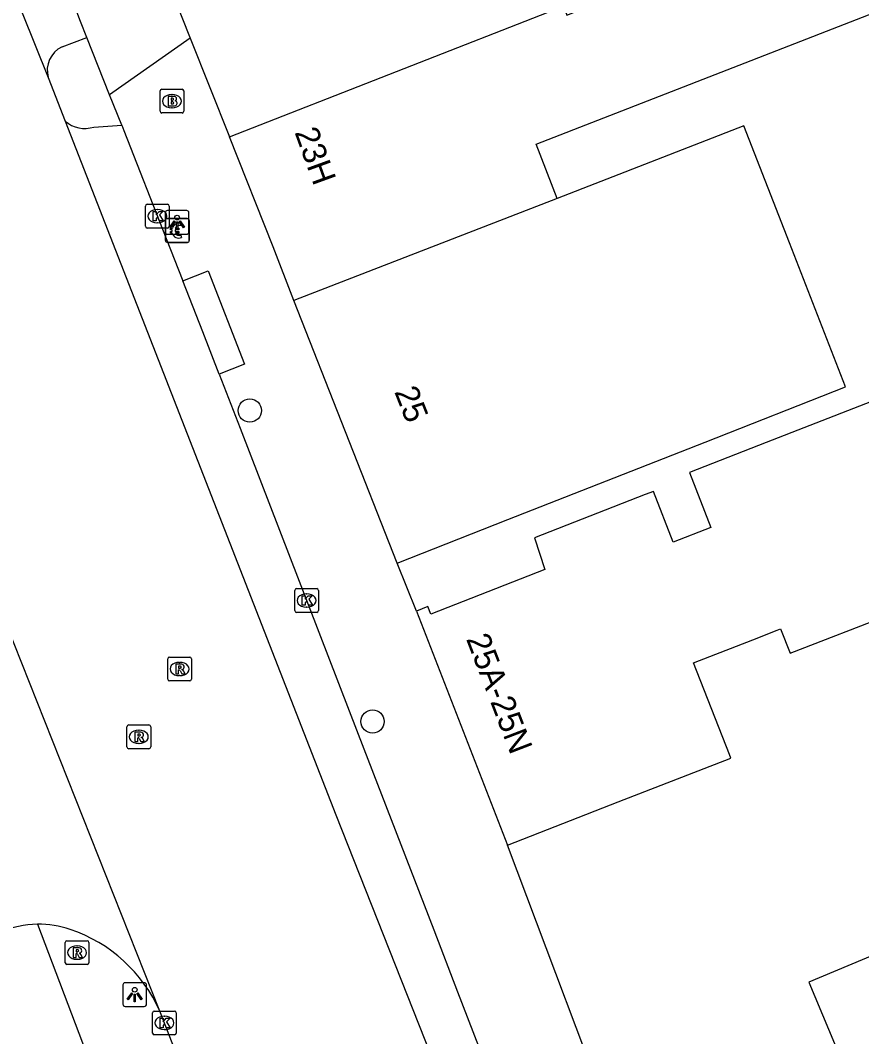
# Model space of a CAD drawing. Extents: x 161087 to 161922, y 382574 to 383873.
# Drawn here: x 161740.93 to 161776.33, y 382704.24 to 382747.01 of the extents above; entities that cross this region are included whole.
import ezdxf

# ---------------------------------------------------------------- set-up
doc = ezdxf.new("R2010")
doc.units = 0
for name, color, linetype in [('IMGEO_Betaalautomaat', 7, 'Continuous'), ('IMGEO_Boom', 7, 'Continuous'), ('IMGEO_Brandkraan', 7, 'Continuous'), ('IMGEO_Kolk', 7, 'Continuous'), ('IMGEO_Lichtpunt', 7, 'Continuous'), ('IMGEO_Pand', 7, 'Continuous'), ('IMGEO_Pand_nummerreeks', 7, 'Continuous'), ('IMGEO_Rijbaan_lokaal_open', 7, 'Continuous'), ('IMGEO_Rioolput', 7, 'Continuous'), ('IMGEO_Voetpad_open', 7, 'Continuous')]:
    doc.layers.add(name, color=color, linetype=linetype)

msp = doc.modelspace()

# ---------------------------------------------------------------- linework, layer by layer
at = {"layer": 'IMGEO_Betaalautomaat'}
for p, q in [((161747.04, 382737.742), (161747.04, 382738.583)), ((161747.04, 382738.583), (161747.04, 382737.742)), ((161747.115, 382738.666), (161747.956, 382738.666)), ((161747.956, 382738.666), (161747.115, 382738.666)), ((161748.039, 382738.592), (161748.039, 382737.751)), ((161748.039, 382737.751), (161748.039, 382738.592)), ((161747.323, 382738.13), (161747.323, 382738.198)), ((161747.444, 382738.198), (161747.444, 382738.13)), ((161747.702, 382738.471), (161747.685, 382738.371)), ((161747.689, 382737.965), (161747.711, 382737.878)), ((161747.965, 382737.667), (161747.124, 382737.667)), ((161747.124, 382737.667), (161747.965, 382737.667))]:
    msp.add_line(p, q, dxfattribs=at)
for points in [[(161747.323, 382738.198), (161747.254, 382738.198), (161747.254, 382738.267), (161747.333, 382738.267)], [(161747.328, 382738.061), (161747.254, 382738.061), (161747.254, 382738.13), (161747.323, 382738.13)], [(161747.455, 382738.267), (161747.602, 382738.267), (161747.602, 382738.198), (161747.444, 382738.198)], [(161747.444, 382738.13), (161747.602, 382738.13), (161747.602, 382738.061), (161747.458, 382738.061)]]:
    msp.add_lwpolyline(points, dxfattribs=at)
for centre, radius, start, end in [((161747.118, 382738.589), 0.0779, 92.4484, 184.2845), ((161747.118, 382738.589), 0.0779, 92.4484, 184.2845), ((161747.962, 382738.589), 0.0779, 2.4484, 94.2845), ((161747.962, 382738.589), 0.0779, 2.4484, 94.2845), ((161747.616, 382738.191), 0.293, 73.014, 165.0139), ((161747.622, 382738.204), 0.179, 69.3236, 159.5683), ((161747.118, 382737.745), 0.0779, 182.4484, 274.2845), ((161747.118, 382737.745), 0.0779, 182.4484, 274.2845), ((161747.589, 382738.116), 0.267, 191.8096, 297.0389), ((161747.622, 382738.131), 0.179, 202.7625, 291.8693), ((161747.962, 382737.745), 0.0779, 272.4484, 4.2845), ((161747.962, 382737.745), 0.0779, 272.4484, 4.2845)]:
    msp.add_arc(centre, radius, start, end, dxfattribs=at)
at = {"layer": 'IMGEO_Boom'}
for centre in [(161750.589, 382730.591), (161755.753, 382717.503)]:
    msp.add_circle(centre, 0.489, dxfattribs=at)
at = {"layer": 'IMGEO_Brandkraan'}
for p, q in [((161746.886, 382744.113), (161747.738, 382744.113)), ((161746.811, 382743.187), (161746.811, 382744.039)), ((161747.299, 382743.893), (161747.324, 382743.893)), ((161747.812, 382744.039), (161747.812, 382743.187)), ((161747.322, 382743.333), (161747.297, 382743.333)), ((161747.738, 382743.113), (161746.886, 382743.113))]:
    msp.add_line(p, q, dxfattribs=at)
for points in [[(161746.886, 382744.113), (161747.738, 382744.113)], [(161746.811, 382743.187), (161746.811, 382744.039)], [(161747.159, 382743.813), (161747.159, 382743.413), (161747.372, 382743.413)], [(161747.39, 382743.813), (161747.159, 382743.813)], [(161747.338, 382743.732), (161747.284, 382743.732), (161747.284, 382743.656)], [(161747.812, 382744.039), (161747.812, 382743.187)], [(161747.284, 382743.656), (161747.337, 382743.656)], [(161747.346, 382743.58), (161747.284, 382743.58), (161747.284, 382743.499)], [(161747.284, 382743.499), (161747.346, 382743.499)], [(161747.738, 382743.113), (161746.886, 382743.113)]]:
    msp.add_lwpolyline(points, dxfattribs=at)
for centre, radius, start, end in [((161746.888, 382744.037), 0.0765, 91.552, 178.448), ((161746.888, 382744.037), 0.0765, 91.552, 178.448), ((161747.736, 382744.037), 0.0765, 1.552, 88.448), ((161747.736, 382744.037), 0.0765, 1.552, 88.448), ((161747.339, 382743.694), 0.0379, 267.8285, 90.9355), ((161747.394, 382743.668), 0.145, 59.4692, 91.5367), ((161747.419, 382743.715), 0.0922, 285.5137, 58.1501), ((161747.347, 382743.539), 0.0404, 269.8759, 90.5077), ((161747.378, 382743.664), 0.251, 268.6676, 293.5347), ((161747.424, 382743.523), 0.105, 301.3115, 78.989), ((161746.888, 382743.189), 0.0765, 181.552, 268.448), ((161746.888, 382743.189), 0.0765, 181.552, 268.448), ((161747.736, 382743.189), 0.0765, 271.552, 358.448), ((161747.736, 382743.189), 0.0765, 271.552, 358.448)]:
    msp.add_arc(centre, radius, start, end, dxfattribs=at)
for centre, major_axis, ratio, start_param, end_param in [((161747.298, 382743.613), (-0.387, 0.002), 0.722429, 4.712389, 7.853982), ((161747.323, 382743.613), (-0.39, 0.002), 0.717154, 1.570796, 4.712389)]:
    msp.add_ellipse(centre, major_axis=major_axis, ratio=ratio, start_param=start_param, end_param=end_param, dxfattribs=at)
at = {"layer": 'IMGEO_Kolk'}
for p, q in [((161746.198, 382738.345), (161746.198, 382739.197)), ((161746.273, 382739.271), (161747.125, 382739.271)), ((161746.686, 382739.051), (161746.711, 382739.051)), ((161747.199, 382739.197), (161747.199, 382738.345)), ((161747.125, 382738.271), (161746.273, 382738.271)), ((161746.709, 382738.491), (161746.684, 382738.491)), ((161752.476, 382722.17), (161752.476, 382723.022)), ((161752.551, 382723.096), (161753.403, 382723.096)), ((161752.964, 382722.876), (161752.989, 382722.876)), ((161753.477, 382723.022), (161753.477, 382722.17)), ((161752.987, 382722.316), (161752.962, 382722.316)), ((161753.403, 382722.096), (161752.551, 382722.096)), ((161746.494, 382704.391), (161746.494, 382705.243)), ((161746.569, 382705.317), (161747.421, 382705.317)), ((161747.495, 382705.243), (161747.495, 382704.391)), ((161746.982, 382705.097), (161747.007, 382705.097)), ((161747.005, 382704.537), (161746.98, 382704.537)), ((161747.421, 382704.317), (161746.569, 382704.317))]:
    msp.add_line(p, q, dxfattribs=at)
for points in [[(161746.198, 382738.345), (161746.198, 382739.197)], [(161746.273, 382739.271), (161747.125, 382739.271)], [(161747.199, 382739.197), (161747.199, 382738.345)], [(161746.519, 382738.971), (161746.642, 382738.971), (161746.642, 382738.82), (161746.772, 382738.971), (161746.936, 382738.971), (161746.79, 382738.82), (161746.943, 382738.571), (161746.791, 382738.571), (161746.706, 382738.735), (161746.642, 382738.668), (161746.642, 382738.571), (161746.519, 382738.571), (161746.519, 382738.971)], [(161747.125, 382738.271), (161746.273, 382738.271)], [(161752.476, 382722.17), (161752.476, 382723.022)], [(161752.551, 382723.096), (161753.403, 382723.096)], [(161752.797, 382722.796), (161752.92, 382722.796), (161752.92, 382722.645), (161753.05, 382722.796), (161753.214, 382722.796), (161753.068, 382722.645), (161753.221, 382722.396), (161753.069, 382722.396), (161752.984, 382722.56), (161752.92, 382722.493), (161752.92, 382722.396), (161752.797, 382722.396), (161752.797, 382722.796)], [(161753.477, 382723.022), (161753.477, 382722.17)], [(161753.403, 382722.096), (161752.551, 382722.096)], [(161746.494, 382704.391), (161746.494, 382705.243)], [(161746.569, 382705.317), (161747.421, 382705.317)], [(161747.495, 382705.243), (161747.495, 382704.391)], [(161746.815, 382705.017), (161746.938, 382705.017), (161746.938, 382704.866), (161747.068, 382705.017), (161747.232, 382705.017), (161747.086, 382704.866), (161747.239, 382704.617), (161747.087, 382704.617), (161747.002, 382704.781), (161746.938, 382704.714), (161746.938, 382704.617), (161746.815, 382704.617), (161746.815, 382705.017)], [(161747.421, 382704.317), (161746.569, 382704.317)]]:
    msp.add_lwpolyline(points, dxfattribs=at)
for centre, start, end in [((161746.275, 382739.195), 91.552, 178.448), ((161746.275, 382739.195), 91.552, 178.448), ((161747.123, 382739.195), 1.552, 88.448), ((161747.123, 382739.195), 1.552, 88.448), ((161746.275, 382738.347), 181.552, 268.448), ((161746.275, 382738.347), 181.552, 268.448), ((161747.123, 382738.347), 271.552, 358.448), ((161747.123, 382738.347), 271.552, 358.448), ((161752.553, 382723.02), 91.552, 178.448), ((161752.553, 382723.02), 91.552, 178.448), ((161753.401, 382723.02), 1.552, 88.448), ((161753.401, 382723.02), 1.552, 88.448), ((161752.553, 382722.172), 181.552, 268.448), ((161752.553, 382722.172), 181.552, 268.448), ((161753.401, 382722.172), 271.552, 358.448), ((161753.401, 382722.172), 271.552, 358.448), ((161746.571, 382705.241), 91.552, 178.448), ((161746.571, 382705.241), 91.552, 178.448), ((161747.419, 382705.241), 1.552, 88.448), ((161747.419, 382705.241), 1.552, 88.448), ((161746.571, 382704.393), 181.552, 268.448), ((161746.571, 382704.393), 181.552, 268.448), ((161747.419, 382704.393), 271.552, 358.448), ((161747.419, 382704.393), 271.552, 358.448)]:
    msp.add_arc(centre, 0.0765, start, end, dxfattribs=at)
for centre, major_axis, ratio, start_param, end_param in [((161746.685, 382738.771), (-0.387, 0.002), 0.722429, 4.712389, 7.853982), ((161746.71, 382738.771), (-0.39, 0.002), 0.717154, 1.570796, 4.712389), ((161752.963, 382722.596), (-0.387, 0.002), 0.722429, 4.712389, 7.853982), ((161752.988, 382722.596), (-0.39, 0.002), 0.717154, 1.570796, 4.712389), ((161746.981, 382704.817), (-0.387, 0.002), 0.722429, 4.712389, 7.853982), ((161747.006, 382704.817), (-0.39, 0.002), 0.717154, 1.570796, 4.712389)]:
    msp.add_ellipse(centre, major_axis=major_axis, ratio=ratio, start_param=start_param, end_param=end_param, dxfattribs=at)
at = {"layer": 'IMGEO_Lichtpunt'}
for p, q in [((161747.933, 382739.007), (161747.125, 382739.007)), ((161747.933, 382739.007), (161747.125, 382739.007)), ((161747.031, 382738.912), (161747.031, 382738.105)), ((161747.031, 382738.912), (161747.031, 382738.105)), ((161748.027, 382738.105), (161748.027, 382738.912)), ((161748.027, 382738.105), (161748.027, 382738.912)), ((161747.125, 382738.011), (161747.933, 382738.011)), ((161747.125, 382738.011), (161747.933, 382738.011)), ((161746.149, 382706.511), (161745.341, 382706.511)), ((161746.149, 382706.511), (161745.341, 382706.511)), ((161745.247, 382706.416), (161745.247, 382705.609)), ((161745.247, 382706.416), (161745.247, 382705.609)), ((161746.243, 382705.609), (161746.243, 382706.416)), ((161746.243, 382705.609), (161746.243, 382706.416)), ((161745.341, 382705.515), (161746.149, 382705.515)), ((161745.341, 382705.515), (161746.149, 382705.515))]:
    msp.add_line(p, q, dxfattribs=at)
for points in [[(161747.405, 382738.576), (161747.444, 382738.548), (161747.256, 382738.286), (161747.218, 382738.313), (161747.405, 382738.576)], [(161747.617, 382738.548), (161747.655, 382738.575), (161747.842, 382738.313), (161747.803, 382738.285), (161747.617, 382738.548)], [(161747.507, 382738.528), (161747.554, 382738.528), (161747.554, 382738.206), (161747.507, 382738.206), (161747.507, 382738.528)], [(161745.621, 382706.08), (161745.66, 382706.052), (161745.472, 382705.79), (161745.434, 382705.817), (161745.621, 382706.08)], [(161745.833, 382706.052), (161745.871, 382706.079), (161746.058, 382705.817), (161746.019, 382705.789), (161745.833, 382706.052)], [(161745.723, 382706.032), (161745.77, 382706.032), (161745.77, 382705.71), (161745.723, 382705.71), (161745.723, 382706.032)]]:
    msp.add_lwpolyline(points, dxfattribs=at)
for centre in [(161747.53, 382738.71), (161745.746, 382706.214)]:
    msp.add_circle(centre, 0.0994, dxfattribs=at)
for centre, start, end in [((161747.125, 382738.912), 90, 180), ((161747.125, 382738.912), 90, 180), ((161747.933, 382738.912), 0, 90), ((161747.933, 382738.912), 0, 90), ((161747.125, 382738.105), 180, 270), ((161747.125, 382738.105), 180, 270), ((161747.933, 382738.105), 270, 0), ((161747.933, 382738.105), 270, 360), ((161745.341, 382706.416), 90, 180), ((161745.341, 382706.416), 90, 180), ((161746.149, 382706.416), 0, 90), ((161746.149, 382706.416), 0, 90), ((161745.341, 382705.609), 180, 270), ((161745.341, 382705.609), 180, 270), ((161746.149, 382705.609), 270, 0), ((161746.149, 382705.609), 270, 360)]:
    msp.add_arc(centre, 0.0946, start, end, dxfattribs=at)
at = {"layer": 'IMGEO_Pand'}
for points in [[(161749.728, 382742.115), (161763.782, 382747.61), (161763.929, 382747.233), (161786.294, 382756.038)], [(161763.515, 382739.519), (161762.633, 382741.801), (161783.647, 382750), (161785.222, 382750.626), (161785.092, 382750.952), (161787.843, 382752.05), (161786.294, 382756.038)], [(161747.346, 382748.113), (161748.078, 382746.268)], [(161748.078, 382746.268), (161749.728, 382742.115)], [(161756.788, 382724.168), (161761.442, 382725.999), (161769.742, 382729.263), (161775.656, 382731.589), (161773.294, 382737.652), (161771.376, 382742.575), (161763.515, 382739.519)], [(161752.444, 382735.215), (161751.568, 382737.483), (161749.728, 382742.115)], [(161763.515, 382739.519), (161757.105, 382737.027), (161752.444, 382735.215)], [(161788.77, 382735.655), (161772.311, 382729.242), (161769.081, 382727.983), (161769.983, 382725.667), (161768.401, 382725.051), (161767.568, 382727.188), (161767.219, 382727.052), (161762.56, 382725.236), (161762.996, 382723.894), (161758.198, 382722.024), (161758.076, 382722.338), (161757.599, 382722.152)], [(161756.788, 382724.168), (161752.444, 382735.215)], [(161757.599, 382722.152), (161761.433, 382712.304)], [(161761.433, 382712.304), (161766.092, 382714.119), (161770.821, 382715.962), (161770.763, 382716.112), (161769.259, 382719.973), (161771.752, 382720.945), (161772.775, 382721.343), (161772.921, 382721.4), (161773.321, 382720.372), (161777.602, 382722.04)], [(161787.005, 382699.938), (161784.706, 382705.422), (161787.258, 382706.492), (161785.598, 382710.452), (161785.528, 382710.619), (161789.523, 382712.339), (161788.237, 382715.327), (161787.603, 382715.06), (161777.137, 382710.655), (161778.153, 382708.232), (161774.101, 382706.534), (161778.499, 382696.044)]]:
    msp.add_lwpolyline(points, dxfattribs=at)
at = {"layer": 'IMGEO_Rijbaan_lokaal_open'}
for points in [[(161725.319, 382787.311), (161739.937, 382750), (161742.111, 382744.609)], [(161742.111, 382744.609), (161742.826, 382742.772)], [(161742.826, 382742.772), (161754.209, 382713.572), (161768.441, 382677.581), (161785.32, 382634.34), (161787.244, 382635.106)], [(161746.805, 382705.307), (161739.688, 382723.21)], [(161749.972, 382697.162), (161746.805, 382705.307)]]:
    msp.add_lwpolyline(points, dxfattribs=at)
for centre, radius, start, end in [((161741.717, 382704.742), 4.229, 90.8379, 112.8002), ((161741.701, 382704.785), 4.186, 71.4175, 90.6287), ((161740.989, 382702.729), 6.362, 23.9023, 71.2394)]:
    msp.add_arc(centre, radius, start, end, dxfattribs=at)
at = {"layer": 'IMGEO_Rioolput'}
for p, q in [((161747.208, 382720.213), (161748.06, 382720.213)), ((161747.133, 382719.287), (161747.133, 382720.139)), ((161747.621, 382719.993), (161747.646, 382719.993)), ((161748.134, 382720.139), (161748.134, 382719.287)), ((161747.644, 382719.433), (161747.619, 382719.433)), ((161748.06, 382719.213), (161747.208, 382719.213)), ((161745.417, 382716.43), (161745.417, 382717.282)), ((161745.492, 382717.356), (161746.344, 382717.356)), ((161746.418, 382717.282), (161746.418, 382716.43)), ((161745.905, 382717.136), (161745.93, 382717.136)), ((161746.344, 382716.356), (161745.492, 382716.356)), ((161745.928, 382716.576), (161745.903, 382716.576)), ((161742.82, 382707.35), (161742.82, 382708.202)), ((161742.895, 382708.276), (161743.747, 382708.276)), ((161743.821, 382708.202), (161743.821, 382707.35)), ((161743.308, 382708.056), (161743.333, 382708.056)), ((161743.331, 382707.496), (161743.306, 382707.496)), ((161743.747, 382707.276), (161742.895, 382707.276))]:
    msp.add_line(p, q, dxfattribs=at)
for points in [[(161747.208, 382720.213), (161748.06, 382720.213)], [(161747.133, 382719.287), (161747.133, 382720.139)], [(161747.722, 382719.911), (161747.47, 382719.913), (161747.47, 382719.513)], [(161747.648, 382719.832), (161747.594, 382719.832), (161747.594, 382719.751)], [(161747.594, 382719.751), (161747.646, 382719.751)], [(161748.134, 382720.139), (161748.134, 382719.287)], [(161747.47, 382719.513), (161747.594, 382719.513), (161747.594, 382719.675), (161747.605, 382719.675)], [(161747.652, 382719.646), (161747.723, 382719.513), (161747.863, 382719.513), (161747.798, 382719.639)], [(161748.06, 382719.213), (161747.208, 382719.213)], [(161745.417, 382716.43), (161745.417, 382717.282)], [(161745.492, 382717.356), (161746.344, 382717.356)], [(161746.418, 382717.282), (161746.418, 382716.43)], [(161746.006, 382717.054), (161745.754, 382717.056), (161745.754, 382716.656)], [(161745.754, 382716.656), (161745.878, 382716.656), (161745.878, 382716.818), (161745.889, 382716.818)], [(161745.932, 382716.975), (161745.878, 382716.975), (161745.878, 382716.894)], [(161745.878, 382716.894), (161745.93, 382716.894)], [(161745.936, 382716.789), (161746.007, 382716.656), (161746.147, 382716.656), (161746.082, 382716.782)], [(161746.344, 382716.356), (161745.492, 382716.356)], [(161742.82, 382707.35), (161742.82, 382708.202)], [(161742.895, 382708.276), (161743.747, 382708.276)], [(161743.821, 382708.202), (161743.821, 382707.35)], [(161743.409, 382707.974), (161743.157, 382707.976), (161743.157, 382707.576)], [(161743.335, 382707.895), (161743.281, 382707.895), (161743.281, 382707.814)], [(161743.281, 382707.814), (161743.333, 382707.814)], [(161743.157, 382707.576), (161743.281, 382707.576), (161743.281, 382707.738), (161743.292, 382707.738)], [(161743.339, 382707.709), (161743.41, 382707.576), (161743.55, 382707.576), (161743.485, 382707.702)], [(161743.747, 382707.276), (161742.895, 382707.276)]]:
    msp.add_lwpolyline(points, dxfattribs=at)
for centre, radius, start, end in [((161747.21, 382720.137), 0.0765, 91.552, 178.448), ((161747.21, 382720.137), 0.0765, 91.552, 178.448), ((161748.058, 382720.137), 0.0765, 1.552, 88.448), ((161748.058, 382720.137), 0.0765, 1.552, 88.448), ((161747.63, 382719.94), 0.19, 274.7715, 282.9687), ((161747.654, 382719.736), 0.0964, 77.0061, 93.1865), ((161747.668, 382719.793), 0.0378, 276.6634, 79.6772), ((161747.721, 382719.801), 0.109, 350.3612, 89.416), ((161747.719, 382719.801), 0.112, 277.5842, 350.9817), ((161747.604, 382719.622), 0.0533, 26.0293, 88.6989), ((161747.703, 382719.586), 0.108, 29.5134, 73.7905), ((161747.21, 382719.289), 0.0765, 181.552, 268.448), ((161747.21, 382719.289), 0.0765, 181.552, 268.448), ((161748.058, 382719.289), 0.0765, 271.552, 358.448), ((161748.058, 382719.289), 0.0765, 271.552, 358.448), ((161745.494, 382717.28), 0.0765, 91.552, 178.448), ((161745.494, 382717.28), 0.0765, 91.552, 178.448), ((161746.342, 382717.28), 0.0765, 1.552, 88.448), ((161746.342, 382717.28), 0.0765, 1.552, 88.448), ((161745.888, 382716.765), 0.0533, 26.0293, 88.6989), ((161745.914, 382717.083), 0.19, 274.7715, 282.9687), ((161745.938, 382716.879), 0.0964, 77.0061, 93.1865), ((161745.952, 382716.936), 0.0378, 276.6634, 79.6772), ((161746.005, 382716.944), 0.109, 350.3612, 89.416), ((161746.003, 382716.944), 0.112, 277.5842, 350.9817), ((161745.987, 382716.729), 0.108, 29.5134, 73.7905), ((161745.494, 382716.432), 0.0765, 181.552, 268.448), ((161745.494, 382716.432), 0.0765, 181.552, 268.448), ((161746.342, 382716.432), 0.0765, 271.552, 358.448), ((161746.342, 382716.432), 0.0765, 271.552, 358.448), ((161742.897, 382708.2), 0.0765, 91.552, 178.448), ((161742.897, 382708.2), 0.0765, 91.552, 178.448), ((161743.745, 382708.2), 0.0765, 1.552, 88.448), ((161743.745, 382708.2), 0.0765, 1.552, 88.448), ((161743.317, 382708.003), 0.19, 274.7715, 282.9687), ((161743.341, 382707.799), 0.0964, 77.0061, 93.1865), ((161743.355, 382707.856), 0.0378, 276.6634, 79.6772), ((161743.408, 382707.864), 0.109, 350.3612, 89.416), ((161743.406, 382707.864), 0.112, 277.5842, 350.9817), ((161743.39, 382707.649), 0.108, 29.5134, 73.7905), ((161742.897, 382707.352), 0.0765, 181.552, 268.448), ((161742.897, 382707.352), 0.0765, 181.552, 268.448), ((161743.291, 382707.685), 0.0533, 26.0293, 88.6989), ((161743.745, 382707.352), 0.0765, 271.552, 358.448), ((161743.745, 382707.352), 0.0765, 271.552, 358.448)]:
    msp.add_arc(centre, radius, start, end, dxfattribs=at)
for centre, major_axis, ratio, start_param, end_param in [((161747.62, 382719.713), (-0.387, 0.002), 0.722429, 4.712389, 7.853982), ((161747.645, 382719.713), (-0.39, 0.002), 0.717154, 1.570796, 4.712389), ((161745.904, 382716.856), (-0.387, 0.002), 0.722429, 4.712389, 7.853982), ((161745.929, 382716.856), (-0.39, 0.002), 0.717154, 1.570796, 4.712389), ((161743.307, 382707.776), (-0.387, 0.002), 0.722429, 4.712389, 7.853982), ((161743.332, 382707.776), (-0.39, 0.002), 0.717154, 1.570796, 4.712389)]:
    msp.add_ellipse(centre, major_axis=major_axis, ratio=ratio, start_param=start_param, end_param=end_param, dxfattribs=at)
at = {"layer": 'IMGEO_Voetpad_open'}
for points in [[(161743.726, 382746.292), (161743.459, 382746.961), (161742.323, 382750), (161741.399, 382752.473)], [(161742.688, 382745.897), (161743.726, 382746.292)], [(161744.692, 382743.875), (161743.726, 382746.292)], [(161748.078, 382746.268), (161744.692, 382743.875)], [(161745.204, 382742.595), (161744.692, 382743.875)], [(161744.027, 382742.521), (161745.204, 382742.595)], [(161745.204, 382742.595), (161745.292, 382742.374), (161747.065, 382737.827), (161747.764, 382736.047)], [(161747.764, 382736.047), (161748.835, 382736.465), (161750.365, 382732.545), (161749.294, 382732.127)], [(161749.294, 382732.127), (161748.608, 382733.899), (161747.764, 382736.047)], [(161749.294, 382732.127), (161750.176, 382729.847), (161755.146, 382716.973), (161758.324, 382708.735), (161759.331, 382706.124), (161761.163, 382701.376), (161761.824, 382699.694)], [(161757.599, 382722.152), (161756.788, 382724.168)], [(161775.138, 382676.312), (161771.278, 382686.152), (161761.433, 382712.304)], [(161741.655, 382708.971), (161745.752, 382698.169)]]:
    msp.add_lwpolyline(points, dxfattribs=at)
for centre, radius, start, end in [((161743.151, 382744.916), 1.084, 115.2602, 196.4768), ((161743.645, 382743.694), 1.233, 228.3675, 288.0235)]:
    msp.add_arc(centre, radius, start, end, dxfattribs=at)

# ---------------------------------------------------------------- texts
at = {"layer": 'IMGEO_Pand_nummerreeks'}
for s, rotation, p in [('23H', 289.9831, (161752.463, 382742.304)), ('25', 291.4662, (161756.659, 382731.383)), ('25A-25N', 291.0732, (161759.678, 382720.979))]:
    msp.add_text(s, height=1, rotation=rotation, dxfattribs=at).set_placement(p)

doc.saveas('drawing.dxf')
